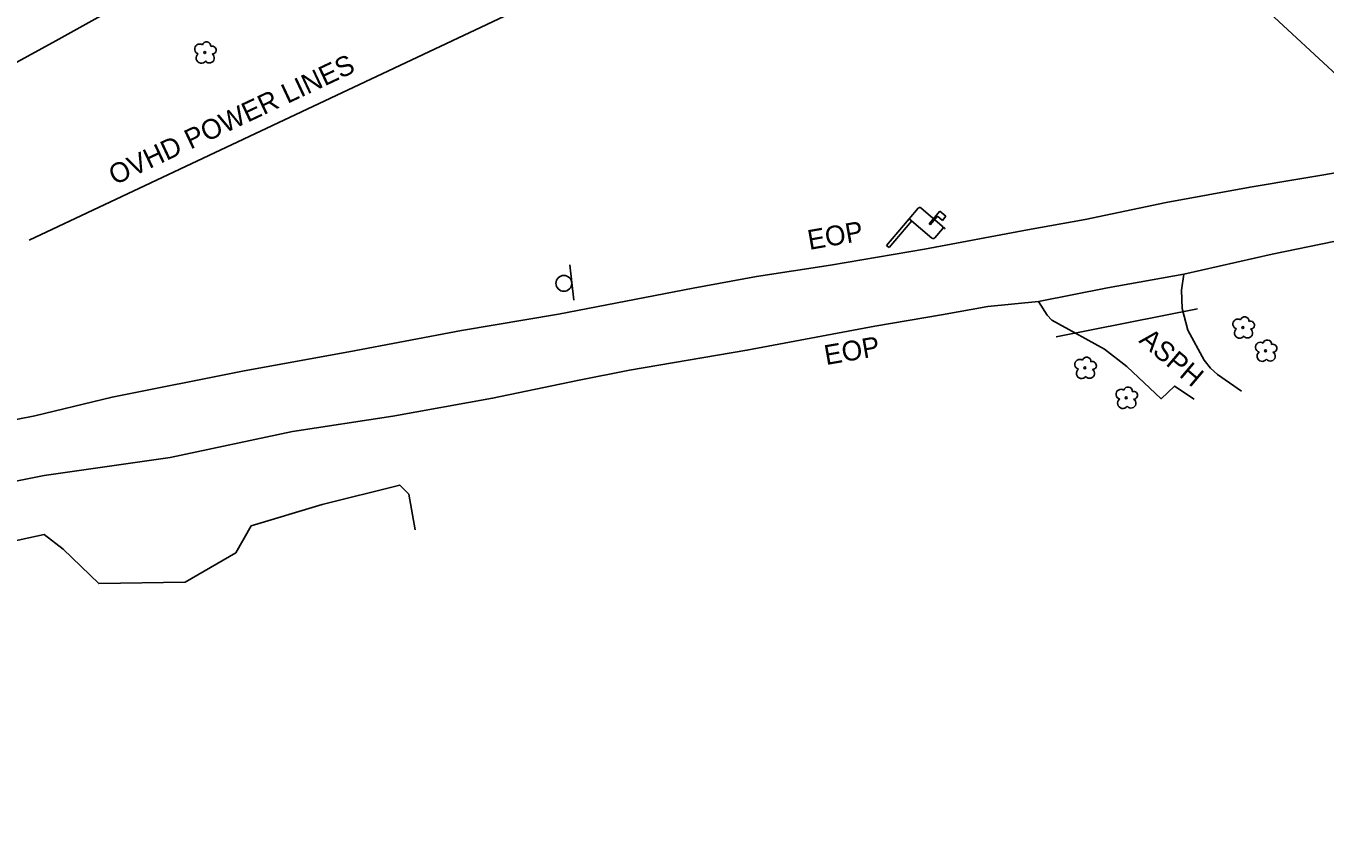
# Model space of a CAD drawing. Extents: x 2076109 to 2080761, y 592812 to 596750.
# Drawn here: x 2076956.7 to 2077285.2, y 595372.9 to 595575.9 of the extents above; entities that cross this region are included whole.
import ezdxf

# ---------------------------------------------------------------- set-up
doc = ezdxf.new("R2010")
doc.units = 0
for name, color, linetype in [('Default', 7, 'Continuous'), ('RD_EX_BldgApp', 7, 'Continuous'), ('RD_EX_DR_Pipe', 7, 'Continuous'), ('RD_EX_Driveway', 7, 'Continuous'), ('RD_EX_Driveway_txCode', 7, 'Continuous'), ('RD_EX_Road', 7, 'Continuous'), ('RD_EX_Road_txCode', 7, 'Continuous'), ('RD_EX_UT', 7, 'Continuous'), ('RD_EX_UT_txCode', 7, 'Continuous'), ('RD_EX_VEG', 7, 'Continuous')]:
    doc.layers.add(name, color=color, linetype=linetype)

msp = doc.modelspace()

# ---------------------------------------------------------------- linework, layer by layer
at = {"layer": 'Default'}
msp.add_arc((2035586.7, 547847.96), 63546.51, 48.5011873, 49.2923126, dxfattribs=at)
msp.add_arc((2035586.7, 547847.96), 63546.51, 48.5011873, 49.2923126, dxfattribs=at)
at = {"layer": 'RD_EX_BldgApp'}
for p, q in [((2077180.05, 595527.17), (2077182.31, 595529.84)), ((2077180.05, 595527.17), (2077182.31, 595529.84)), ((2077183.01, 595529.9), (2077188.41, 595525.33)), ((2077183.01, 595529.9), (2077188.41, 595525.33)), ((2077185.07, 595525.92), (2077187.77, 595529.11)), ((2077185.07, 595525.92), (2077187.77, 595529.11)), ((2077187.77, 595529.11), (2077189.34, 595527.79)), ((2077187.77, 595529.11), (2077189.34, 595527.79)), ((2077180.05, 595527.17), (2077174.35, 595520.44)), ((2077180.05, 595527.17), (2077174.35, 595520.44)), ((2077180.69, 595526.63), (2077174.99, 595519.9)), ((2077180.69, 595526.63), (2077174.99, 595519.9)), ((2077185.82, 595522.28), (2077180.05, 595527.17)), ((2077185.82, 595522.28), (2077180.05, 595527.17)), ((2077185.36, 595525.67), (2077185.07, 595525.92)), ((2077185.36, 595525.67), (2077185.07, 595525.92)), ((2077187.19, 595527.84), (2077185.36, 595525.67)), ((2077187.19, 595527.84), (2077185.36, 595525.67)), ((2077188.47, 595526.76), (2077187.19, 595527.84)), ((2077188.47, 595526.76), (2077187.19, 595527.84)), ((2077189.34, 595527.79), (2077188.47, 595526.76)), ((2077189.34, 595527.79), (2077188.47, 595526.76)), ((2077188.46, 595524.63), (2077186.53, 595522.34)), ((2077188.46, 595524.63), (2077186.53, 595522.34)), ((2077188.46, 595524.63), (2077188.79, 595525.01)), ((2077188.46, 595524.63), (2077188.79, 595525.01)), ((2077188.79, 595525.01), (2077189.17, 595524.69)), ((2077188.79, 595525.01), (2077189.17, 595524.69)), ((2077189.17, 595524.69), (2077189.01, 595524.5)), ((2077189.17, 595524.69), (2077189.01, 595524.5)), ((2077174.35, 595520.44), (2077174.99, 595519.9)), ((2077174.35, 595520.44), (2077174.99, 595519.9)), ((2077095.24, 595506.57), (2077094.23, 595515.51)), ((2077095.24, 595506.57), (2077094.23, 595515.51))]:
    msp.add_line(p, q, dxfattribs=at)
msp.add_circle((2077092.72, 595510.83), 2, dxfattribs=at)
msp.add_circle((2077092.72, 595510.83), 2, dxfattribs=at)
for centre, start, end in [((2077182.69, 595529.52), 49.7592, 139.7592), ((2077182.69, 595529.52), 49.7592, 139.7592), ((2077186.15, 595522.66), 229.7592, 319.7592), ((2077186.15, 595522.66), 229.7592, 319.7592), ((2077188.08, 595524.95), 319.7592, 49.7592), ((2077188.08, 595524.95), 319.7592, 49.7592)]:
    msp.add_arc(centre, 0.5, start, end, dxfattribs=at)
at = {"layer": 'RD_EX_DR_Pipe'}
msp.add_line((2077217.25, 595497.31), (2077253, 595504.37), dxfattribs=at)
msp.add_line((2077217.25, 595497.31), (2077253, 595504.37), dxfattribs=at)
at = {"layer": 'RD_EX_Driveway'}
for points in [[(2077264.14, 595483.58), (2077258.01, 595487.8), (2077256.26, 595489.37), (2077254.65, 595491.38), (2077250.55, 595498.98), (2077249.12, 595504.51), (2077248.91, 595509.1), (2077249.53, 595513.12)], [(2077264.14, 595483.58), (2077258.01, 595487.8), (2077256.26, 595489.37), (2077254.65, 595491.38), (2077250.55, 595498.98), (2077249.12, 595504.51), (2077248.91, 595509.1), (2077249.53, 595513.12)], [(2077212.74, 595506.25), (2077214.99, 595502.77), (2077216.11, 595501.49), (2077222.14, 595498.21), (2077229.44, 595494.23), (2077235.09, 595489.78), (2077243.76, 595481.66), (2077247.17, 595484.88), (2077252.17, 595481.57)], [(2077212.74, 595506.25), (2077214.99, 595502.77), (2077216.11, 595501.49), (2077222.14, 595498.21), (2077229.44, 595494.23), (2077235.09, 595489.78), (2077243.76, 595481.66), (2077247.17, 595484.88), (2077252.17, 595481.57)]]:
    msp.add_lwpolyline(points, dxfattribs=at)
at = {"layer": 'RD_EX_Road'}
for points in [[(2076946.45, 595562.46), (2076964.21, 595572.12), (2076985.67, 595584.13), (2077003.53, 595594.22), (2077020.62, 595603.86), (2077041.5, 595615.67), (2077059.57, 595625.8), (2077078.55, 595636.46), (2077097.33, 595647.01), (2077110.03, 595654.24), (2077127.93, 595664.39), (2077149.02, 595676.34), (2077165.44, 595685.72), (2077186.78, 595697.64), (2077191.37, 595700.15), (2077199.53, 595704.6), (2077201.82, 595704.54), (2077204.49, 595706.23)], [(2076946.45, 595562.46), (2076964.21, 595572.12), (2076985.67, 595584.13), (2077003.53, 595594.22), (2077020.62, 595603.86), (2077041.5, 595615.67), (2077059.57, 595625.8), (2077078.55, 595636.46), (2077097.33, 595647.01), (2077110.03, 595654.24), (2077127.93, 595664.39), (2077149.02, 595676.34), (2077165.44, 595685.72), (2077186.78, 595697.64), (2077191.37, 595700.15), (2077199.53, 595704.6), (2077201.82, 595704.54), (2077204.49, 595706.23)], [(2077125.39, 595509.63), (2077141.44, 595512.58), (2077160.15, 595515.46), (2077183.91, 595519.48), (2077209.96, 595524.36), (2077224.56, 595526.95), (2077245.01, 595531.24), (2077266.28, 595535.2), (2077291.96, 595539.48)], [(2077125.39, 595509.63), (2077141.44, 595512.58), (2077160.15, 595515.46), (2077183.91, 595519.48), (2077209.96, 595524.36), (2077224.56, 595526.95), (2077245.01, 595531.24), (2077266.28, 595535.2), (2077291.96, 595539.48)], [(2077287.49, 595521.43), (2077271.83, 595518.19), (2077249.53, 595513.12), (2077230.25, 595509.67), (2077212.74, 595506.25), (2077199.9, 595504.98), (2077188.2, 595502.89), (2077171.32, 595499.99), (2077138.99, 595493.94), (2077109.29, 595488.87)], [(2077287.49, 595521.43), (2077271.83, 595518.19), (2077249.53, 595513.12), (2077230.25, 595509.67), (2077212.74, 595506.25), (2077199.9, 595504.98), (2077188.2, 595502.89), (2077171.32, 595499.99), (2077138.99, 595493.94), (2077109.29, 595488.87)], [(2077125.39, 595509.63), (2077091.39, 595503.06), (2077066.82, 595498.9), (2077038.34, 595493.55), (2077011.87, 595488.72), (2076978.43, 595482.1), (2076958.9, 595477.35), (2076931.35, 595471.91)], [(2077125.39, 595509.63), (2077091.39, 595503.06), (2077066.82, 595498.9), (2077038.34, 595493.55), (2077011.87, 595488.72), (2076978.43, 595482.1), (2076958.9, 595477.35), (2076931.35, 595471.91)], [(2076711.91, 595438.8), (2076719.56, 595439.35), (2076732.54, 595438.88), (2076752.98, 595437.32), (2076776.45, 595434.66), (2076798.85, 595433.18), (2076807.36, 595433.37), (2076823.93, 595433.71), (2076834.97, 595434.98), (2076841.7, 595436.27), (2076848.64, 595439.18), (2076854.53, 595441.22), (2076887.04, 595447.57), (2076916.77, 595453.57), (2076943.1, 595458.61), (2076961.26, 595462.23), (2076993.16, 595466.83), (2077024.09, 595473.37), (2077049.42, 595477.24), (2077074.7, 595481.8), (2077096.12, 595486.28), (2077109.29, 595488.87)], [(2076711.91, 595438.8), (2076719.56, 595439.35), (2076732.54, 595438.88), (2076752.98, 595437.32), (2076776.45, 595434.66), (2076798.85, 595433.18), (2076807.36, 595433.37), (2076823.93, 595433.71), (2076834.97, 595434.98), (2076841.7, 595436.27), (2076848.64, 595439.18), (2076854.53, 595441.22), (2076887.04, 595447.57), (2076916.77, 595453.57), (2076943.1, 595458.61), (2076961.26, 595462.23), (2076993.16, 595466.83), (2077024.09, 595473.37), (2077049.42, 595477.24), (2077074.7, 595481.8), (2077096.12, 595486.28), (2077109.29, 595488.87)]]:
    msp.add_lwpolyline(points, dxfattribs=at)
at = {"layer": 'RD_EX_UT'}
for p, q in [((2077210.71, 595635.37), (2077493.63, 595372.87)), ((2077210.71, 595635.37), (2077493.63, 595372.87)), ((2076957.46, 595521.79), (2077194.62, 595633.66)), ((2076957.46, 595521.79), (2077194.62, 595633.66))]:
    msp.add_line(p, q, dxfattribs=at)
at = {"layer": 'RD_EX_VEG'}
msp.add_lwpolyline([(2076850.27, 595415.42), (2076850.21, 595415.45), (2076848.41, 595418.09), (2076851.21, 595422.91), (2076877.6, 595428.13), (2076923.27, 595439.11), (2076961.29, 595447.37), (2076966.08, 595443.67), (2076975.06, 595434.92), (2076996.96, 595435.3), (2077009.72, 595442.72), (2077013.66, 595449.51), (2077031.56, 595454.95), (2077051.21, 595459.83), (2077053.49, 595457.52), (2077055.07, 595448.52)], dxfattribs=at)
msp.add_lwpolyline([(2076850.27, 595415.42), (2076850.21, 595415.45), (2076848.41, 595418.09), (2076851.21, 595422.91), (2076877.6, 595428.13), (2076923.27, 595439.11), (2076961.29, 595447.37), (2076966.08, 595443.67), (2076975.06, 595434.92), (2076996.96, 595435.3), (2077009.72, 595442.72), (2077013.66, 595449.51), (2077031.56, 595454.95), (2077051.21, 595459.83), (2077053.49, 595457.52), (2077055.07, 595448.52)], dxfattribs=at)
for centre in [(2077001.87, 595569.19), (2077001.87, 595569.19), (2077264.47, 595499.65), (2077264.47, 595499.65), (2077270.18, 595493.81), (2077270.18, 595493.81), (2077224.5, 595489.46), (2077224.5, 595489.46), (2077234.93, 595481.91), (2077234.93, 595481.91)]:
    msp.add_circle(centre, 0.25, dxfattribs=at)
for centre, radius, start, end in [((2077002.33, 595570.83), 1.08, 354.6037, 164.3834), ((2077002.33, 595570.83), 1.08, 354.6037, 164.3834), ((2077000.58, 595570.08), 1.26, 56.0792, 254.3614), ((2077000.58, 595570.08), 1.26, 56.0792, 254.3614), ((2077001.03, 595567.81), 1.32, 126.51, 325.3863), ((2077001.03, 595567.81), 1.32, 126.51, 325.3863), ((2077003.09, 595567.78), 1.22, 216.1941, 57.732), ((2077003.09, 595567.78), 1.22, 216.1941, 57.732), ((2077003.77, 595569.81), 0.995, 268.39, 111.6741), ((2077003.77, 595569.81), 0.995, 268.39, 111.6741), ((2077263.18, 595500.54), 1.26, 56.211, 254.4932), ((2077263.18, 595500.54), 1.26, 56.211, 254.4932), ((2077263.63, 595498.28), 1.32, 126.6419, 325.5182), ((2077263.63, 595498.28), 1.32, 126.6419, 325.5182), ((2077264.92, 595501.3), 1.08, 354.7355, 164.5153), ((2077264.92, 595501.3), 1.08, 354.7355, 164.5153), ((2077265.69, 595498.25), 1.22, 216.3259, 57.8639), ((2077265.69, 595498.25), 1.22, 216.3259, 57.8639), ((2077266.37, 595500.28), 0.995, 268.5218, 111.806), ((2077266.37, 595500.28), 0.995, 268.5218, 111.806), ((2077268.89, 595494.7), 1.26, 56.211, 254.4932), ((2077268.89, 595494.7), 1.26, 56.211, 254.4932), ((2077270.63, 595495.45), 1.08, 354.7355, 164.5153), ((2077270.63, 595495.45), 1.08, 354.7355, 164.5153), ((2077269.34, 595492.43), 1.32, 126.6419, 325.5182), ((2077269.34, 595492.43), 1.32, 126.6419, 325.5182), ((2077271.41, 595492.4), 1.22, 216.3259, 57.8639), ((2077271.41, 595492.4), 1.22, 216.3259, 57.8639), ((2077272.08, 595494.43), 0.995, 268.5218, 111.806), ((2077272.08, 595494.43), 0.995, 268.5218, 111.806), ((2077223.2, 595490.35), 1.26, 56.211, 254.4932), ((2077223.2, 595490.35), 1.26, 56.211, 254.4932), ((2077224.95, 595491.1), 1.08, 354.7355, 164.5153), ((2077224.95, 595491.1), 1.08, 354.7355, 164.5153), ((2077226.4, 595490.08), 0.995, 268.5218, 111.806), ((2077226.4, 595490.08), 0.995, 268.5218, 111.806), ((2077223.65, 595488.08), 1.32, 126.6419, 325.5182), ((2077223.65, 595488.08), 1.32, 126.6419, 325.5182), ((2077225.72, 595488.05), 1.22, 216.3259, 57.8639), ((2077225.72, 595488.05), 1.22, 216.3259, 57.8639), ((2077233.64, 595482.8), 1.26, 56.211, 254.4932), ((2077233.64, 595482.8), 1.26, 56.211, 254.4932), ((2077235.38, 595483.56), 1.08, 354.7355, 164.5153), ((2077235.38, 595483.56), 1.08, 354.7355, 164.5153), ((2077236.83, 595482.53), 0.995, 268.5218, 111.806), ((2077236.83, 595482.53), 0.995, 268.5218, 111.806), ((2077234.09, 595480.53), 1.32, 126.6419, 325.5182), ((2077234.09, 595480.53), 1.32, 126.6419, 325.5182), ((2077236.16, 595480.51), 1.22, 216.3259, 57.8639), ((2077236.16, 595480.51), 1.22, 216.3259, 57.8639)]:
    msp.add_arc(centre, radius, start, end, dxfattribs=at)

# ---------------------------------------------------------------- texts
at = {"layer": 'RD_EX_Driveway_txCode'}
msp.add_text('ASPH', height=5, rotation=319.7592, dxfattribs=at).set_placement((2077237.91, 595496.1))
msp.add_text('ASPH', height=5, rotation=319.7592, dxfattribs=at).set_placement((2077237.91, 595496.1))
at = {"layer": 'RD_EX_Road_txCode'}
for p in [(2077154.82, 595519.28), (2077154.82, 595519.28), (2077159.03, 595490.16), (2077159.03, 595490.16)]:
    msp.add_text('EOP', height=5, rotation=9.9696, dxfattribs=at).set_placement(p)
at = {"layer": 'RD_EX_UT_txCode'}
msp.add_text('OVHD POWER LINES', height=5, rotation=25.2319, dxfattribs=at).set_placement((2076979.11, 595535.61))
msp.add_text('OVHD POWER LINES', height=5, rotation=25.2319, dxfattribs=at).set_placement((2076979.11, 595535.61))

doc.saveas('drawing.dxf')
